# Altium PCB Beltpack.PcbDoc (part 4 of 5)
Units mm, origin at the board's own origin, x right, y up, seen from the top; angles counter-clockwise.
Board outline 85 x 81 mm, 4 copper layers (Top Layer, Inner-1, Inner_GND, Bottom Layer), stack 1.556 mm thick; 389 components, 291 nets, 1372 pads, 660 vias.
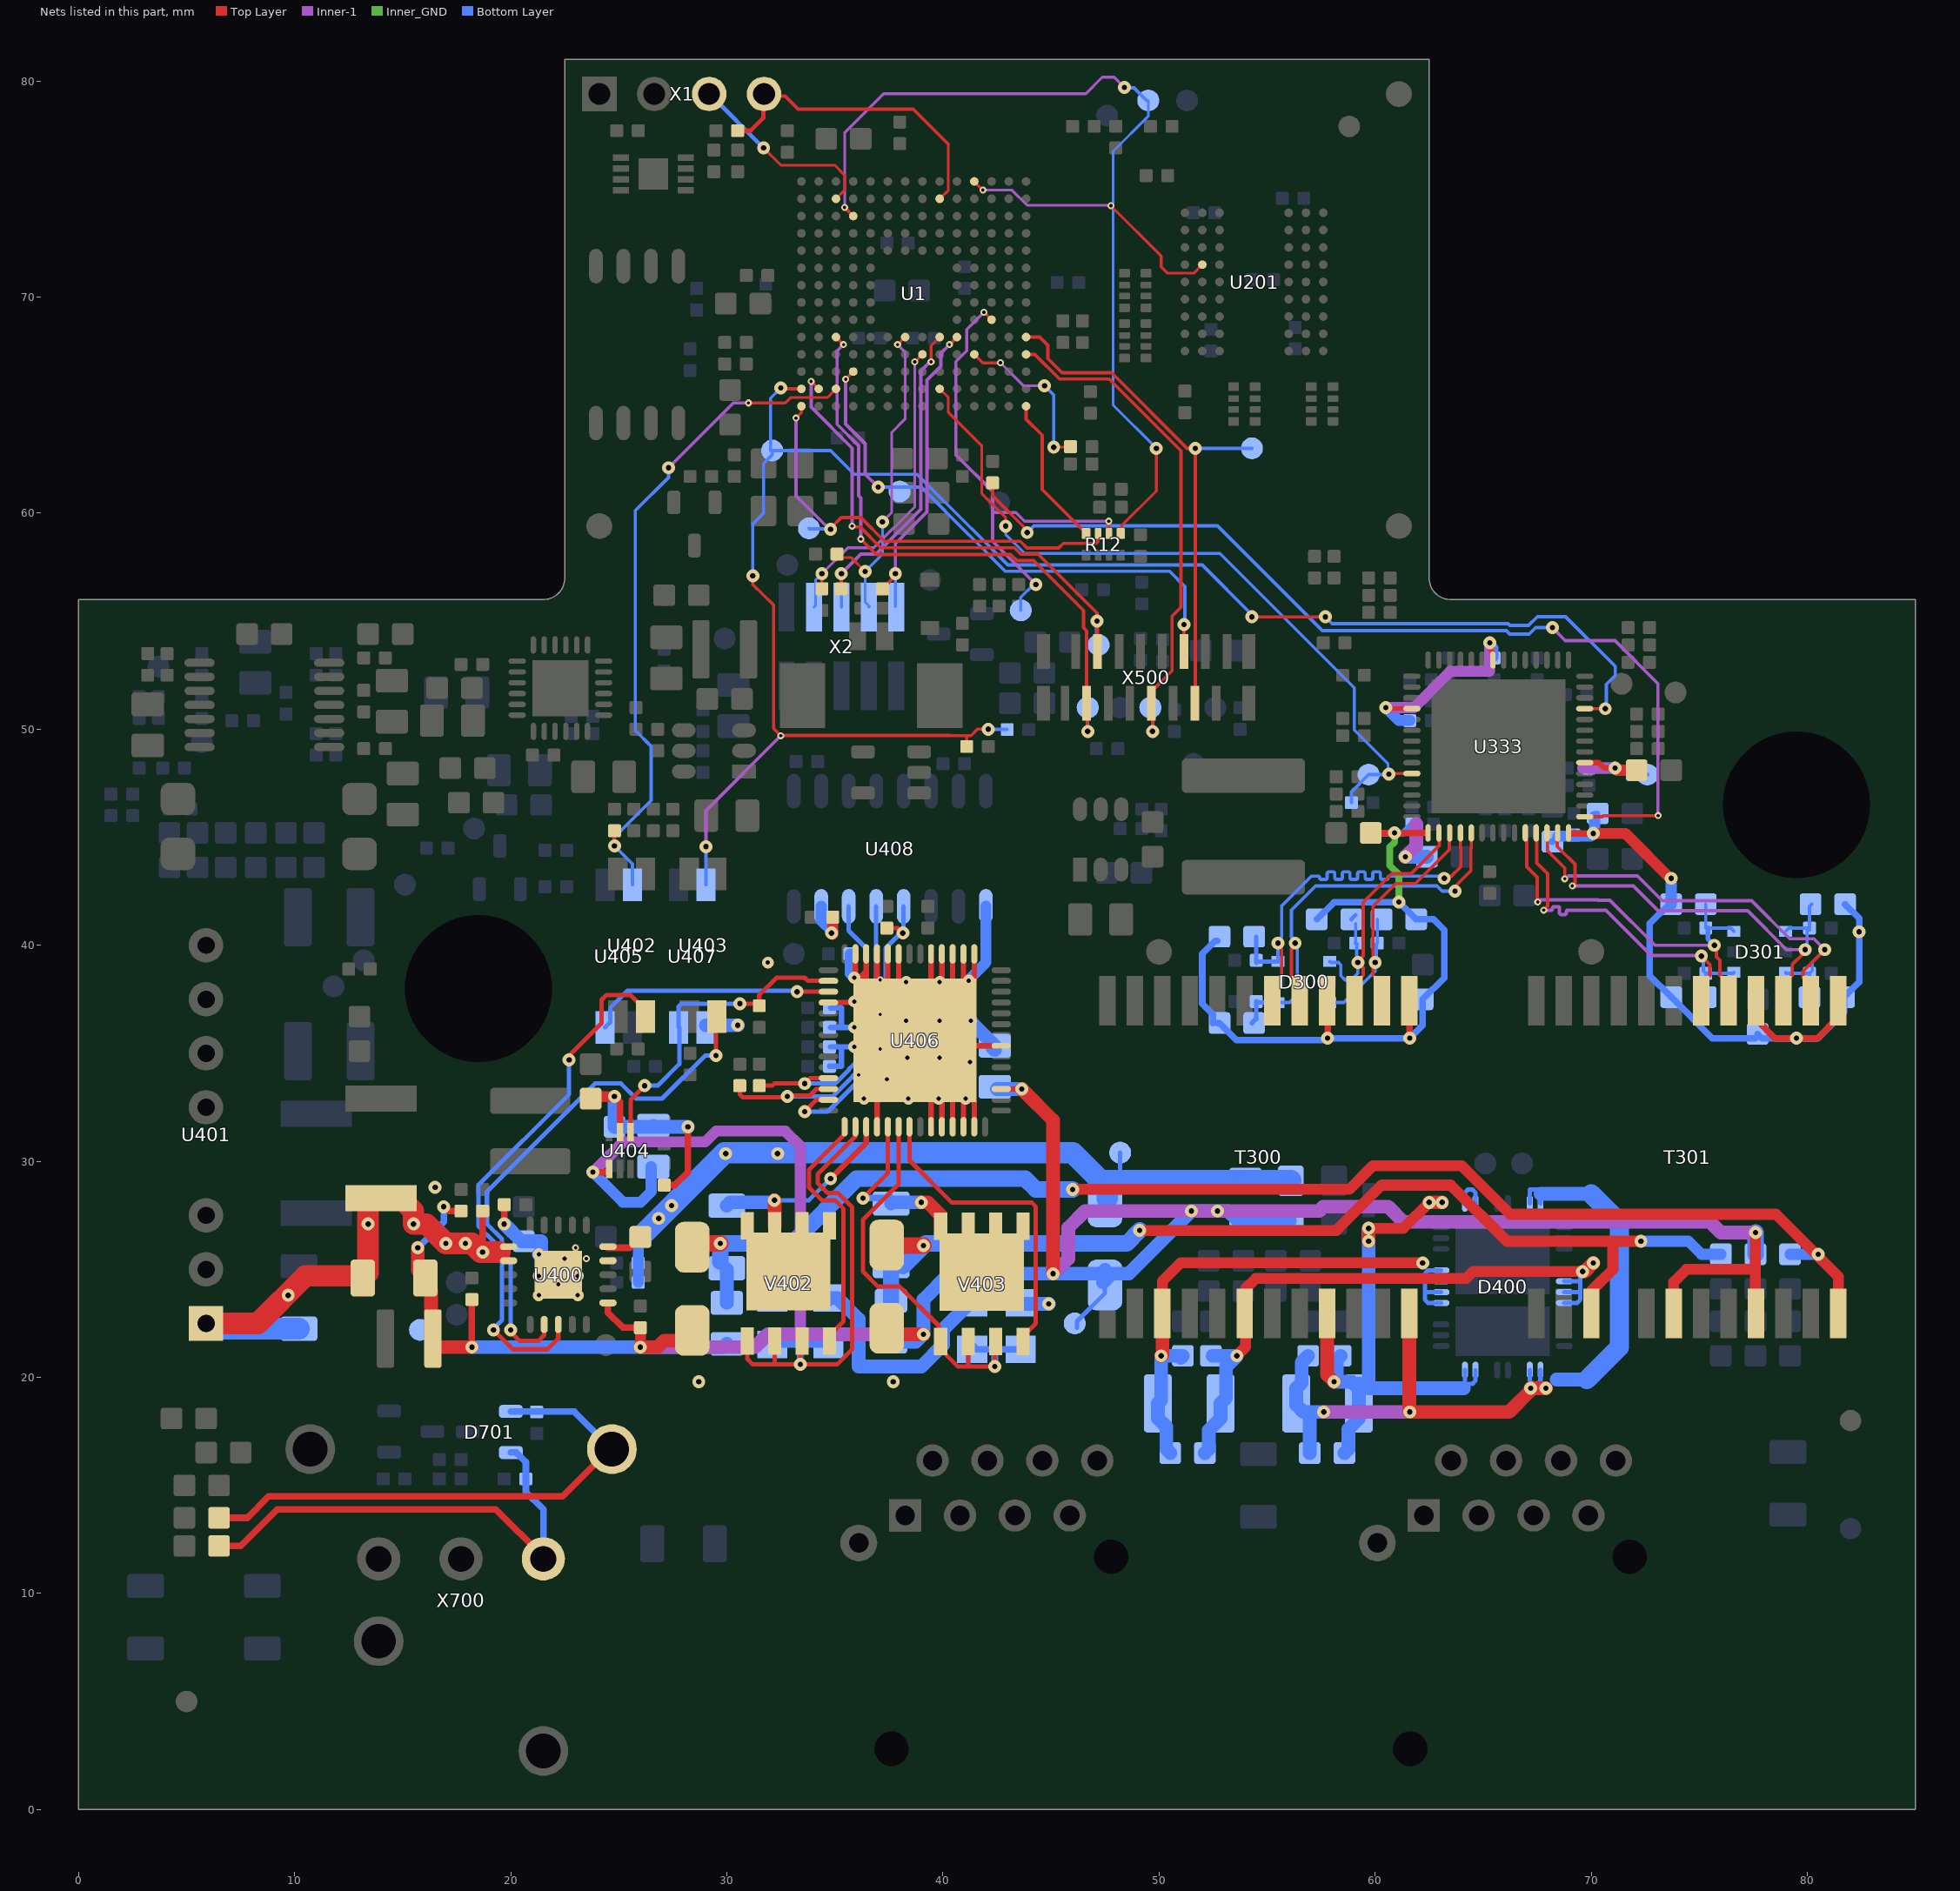
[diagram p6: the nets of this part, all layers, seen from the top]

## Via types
v1: diameter 0.6, hole 0.25, Top Layer to Bottom Layer, 460 vias
v2: diameter 0.325, hole 0.15, Top Layer to Inner-1, 145 vias
v3: diameter 0.55, hole 0.2, Top Layer to Bottom Layer, 41 vias
v4: diameter 0.325, hole 0.15, Top Layer to Inner-1, tented both sides, 8 vias
v5: diameter 1.6, hole 1.016, Top Layer to Bottom Layer, 5 vias
v6: diameter 0.6, hole 0.25, Top Layer to Bottom Layer, tented both sides, 1 vias

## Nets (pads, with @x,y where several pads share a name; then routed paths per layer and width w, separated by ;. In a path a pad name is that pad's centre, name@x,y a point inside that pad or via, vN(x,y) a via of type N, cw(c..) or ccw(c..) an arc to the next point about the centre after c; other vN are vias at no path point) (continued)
PERIPH_NRESET: R17.1 R210.1 TP9.1 U1.A2 U333.11 U407.2 | length 83.9
  Top Layer w0.152: v1(31.2,57.1) 31.2,56.7 31.678,56.222 31.684,56.222 32.162,55.744 32.162,50.038 v4(32.5,49.7) 32.511,49.711 40.312,49.711 40.323,49.7 41.1,49.7 ; v1(32.5,65.8) 32.55,65.75 U1.A2@33.45,65.75 ; R210.1@41.1,49.2 41.1,49.7 ; v1(42.1,50) 41.6,50 41.3,49.7 41.1,49.7 ; v1(54.3,55.2) v1(57.7,55.2) ; U333.11@69.7,50.95 v1(70.65,50.95)
  Inner-1 w0.152: v1(29.035,44.565) 29.035,46.235 v4(32.5,49.7)
  Bottom Layer w0.152: U407.2@29.035,42.8 v1(29.035,44.565) ; v1(31.2,57.1) 31.2,59.5 31.7,60 31.7,62.3 32.1,62.7 TP9.1@32.1,62.9 34.8,62.9 35.9,61.8 38.8,61.8 41.3,59.3 41.307,59.3 43.007,57.6 52,57.6 54.3,55.3 v1(54.3,55.2) ; TP9.1@32.024,62.9 32.024,65.324 v1(32.5,65.8) ; v1(42.1,50) 42.108,49.992 42.966,49.992 R17.1@42.975,49.983 ; v1@57.8,55.1 58.011,54.889 66.147,54.889 66.236,54.8 67.1,54.8 67.511,55.211 68.812,55.211 71.111,52.912 71.111,52.488 70.7,52.077 v1@70.7,51.2
PSE_D1: F400.2 U406.3 V402.5 V402.6 V402.7 V402.8 V402.9 | length 9.6
  Top Layer w0.254: v1(34.8,29.2) 36.45,30.85 U406.3@36.45,31.6
  Top Layer w0.635: v1(32.2,28.2) 32.215,28.185 V402.7@32.215,27.017
  Bottom Layer w0.203: v1(32.2,28.2) 33.8,28.2 v1(34.8,29.2)
  Bottom Layer w0.635: F400.2@30,27.948 30.152,28.1 32.1,28.1 v1(32.2,28.2)
PSE_D2: F401.2 U406.5 V403.5 V403.6 V403.7 V403.8 V403.9 | length 8.2
  Top Layer w0.203: v1(36.3,28.3) 37.45,29.45 U406.5@37.45,31.6 U406.5@37.442,31.592
  Top Layer w0.635: v1(39,28.1) 39.3,28.1 39.895,27.505 V403.8@39.895,26.99
  Bottom Layer w0.203: F401.2@37.5,28.3 F401.2@37.6,28.4
  Bottom Layer w0.305: v1(36.3,28.3) F401.2@37.5,28.3
  Bottom Layer w0.635: F401.2@37.6,28.048 37.652,28.1 v1(39,28.1)
PSE_G1: U406.1 V402.4 | length 11.9
  Top Layer w0.203: V402.4@34.755,21.683 34.755,21.955 35.4,22.6 35.4,27.8 35,28.2 34.4,28.2 33.8,28.8 33.8,29.6 35.45,31.25 U406.1@35.45,31.6
PSE_G2: U406.7 V403.4 | length 14.8
  Top Layer w0.203: U406.7@38.45,31.6 38.45,30.05 40.4,28.1 44.1,28.1 44.3,27.9 44.3,22.5 43.705,21.905 V403.4@43.705,21.656
PSE_N1: C326.1 C414.2 D402.A F400.1 T301.24 | length 63.1
  Top Layer w0.508: v1(46,28.7) 58.8,28.7 59.9,29.8 64,29.8 66.25,27.55 78.55,27.55 81.435,24.665 T301.24@81.435,22.96
  Top Layer w0.635: D402.A@28.275,25.775 D402.A@28.275,25.9 ; D402.A@28.4,25.9 D402.A@28.7,26.2
  Top Layer w0.762: D402.A@28.7,26.2 v1(29.7,26.2)
  Bottom Layer w0.508: F400.1@29.7,25.352 F400.1@30,25.052 ; C326.1@79.2,25.7 v1(80.5,25.7)
  Bottom Layer w0.635: C414.2@30,23.45 F400.1@30,25
  Bottom Layer w0.762: F400.1@29.7,25.352 v1(29.7,26.2) 33,26.2 36,29.2 43.8,29.2 44.3,28.7 v1(46,28.7)
PSE_N2: C327.1 C415.2 D403.A F401.1 T301.15 | length 48.1
  Top Layer w0.508: v1(49.1,26.8) 58.2,26.8 60.3,28.9 63.5,28.9 66.1,26.3 71,26.3 ; T301.15@70.005,22.96 70.005,24.005 71,25 71,26.3 ; v1(72.3,26.3) 71,26.3
  Top Layer w0.635: D403.A@37.6,26.125 D403.A@37.625,26.1
  Top Layer w0.762: D403.A@37.625,26.1 v1(39.1,26.1)
  Bottom Layer w0.508: v1(72.3,26.3) 74.5,26.3 75.1,25.7 C327.1@76,25.7
  Bottom Layer w0.635: F401.1@37.6,25.152 F401.1@38.152,25.152
  Bottom Layer w0.762: C415.2@37.6,23.55 F401.1@37.6,25.152 ; F401.1@38.152,25.152 v1(39.1,26.1) 39.2,26.2 48.5,26.2 v1(49.1,26.8)
PSE_NINT: R418.2 U1.C2 U405.4 | length 31
  Top Layer w0.127: v2(31,65.1) 32.7,65.1 32.949,65.349 34.649,65.349 35,65.7 U1.C2@35.05,65.75
  Top Layer w0.152: v1(24.8,44.6) 24.8,45 ; U1.C2@35,65.7 U1.C2@35.05,65.75
  Inner-1 w0.152: v1(27.3,62.1) 30.3,65.1 v2(31,65.1)
  Bottom Layer w0.152: U405.4@25.635,42.8 25.635,43.765 v1(24.8,44.6) 24.8,45 26.5,46.7 26.5,49.206 25.765,49.942 25.765,60.113 27.3,61.649 v1(27.3,62.1)
PSE_NIRQ: U405.2 U406.45 | length 11.5
  Top Layer w0.203: v1(33.25,37.85) U406.45@34.7,37.85
  Bottom Layer w0.203: U405.2@24.365,36.2 24.6,36.435 24.6,37.1 25.4,37.9 v1@33.3,37.9
PSE_NRES: R400.2 U404.6 U406.44 U407.4 | length 15
  Top Layer w0.203: U404.6@25.55,31.35 25.55,32.85 v1(26.2,33.5) ; v1(30.6,37.3) R400.2@31.5,37.3 ; R400.2@31.5,37.2 31.5,37.7 32.3,38.5 33.6,38.5 33.75,38.35 U406.44@34.7,38.35
  Bottom Layer w0.203: v1(26.2,33.5) 26.8,33.5 27.8,34.5 U407.4@27.8,36.2 ; U407.4@27.765,36.2 27.765,37.165 27.9,37.3 v1(30.6,37.3)
PSE_SCL: R415.2 U406.53 U408.14 | length 13.8
  Top Layer w0.203: R415.2@31.5,33.5 32.1,33.5 32.2,33.6 33.3,33.6 v1@33.7,33.6 ; v1@33.7,33.7 33.85,33.85 U406.53@34.7,33.85
  Bottom Layer w0.203: v1(33.6,33.6) 35.014,33.6 35.664,34.249 35.664,34.286 36.445,35.067 36.445,39.867 35.64,40.672 U408.14@35.64,41.8
PSE_SDAI: R413.2 U406.54 U408.13 | length 16.4
  Top Layer w0.203: R413.2@30.6,33.5 30.6,33.1 30.737,32.963 32.863,32.963 32.944,33.044 33.844,33.044 34.15,33.35 U406.54@34.7,33.35
  Bottom Layer w0.203: v1(32.8,33) 34.892,33 36.745,34.853 36.745,34.867 36.91,35.032 U408.13@36.91,41.8
PSE_SDAO: R404.2 U406.55 U408.12 | length 14.1
  Top Layer w0.203: v1@33.7,32.4 34.15,32.85 U406.55@34.7,32.85 ; R404.2@37.4,40.7 37.5,40.8 37.9,40.8 v1@38.2,40.5
  Bottom Layer w0.203: v1(33.6,32.3) 34.671,32.3 37.345,34.974 37.345,39.867 v1@38.095,40.617 ; v1@38.18,40.702 U408.12@38.18,41.8
  other v1: 38.145,40.567
PSE_SENSE1: R423.1 R424.1 U406.2 V402.1 V402.2 V402.3 | length 23.7
  Top Layer w0.203: V402.1@30.945,21.683 30.945,20.855 31.2,20.6 32.215,20.6 ; V402.2@32.215,21.683 32.215,20.6 ; V402.3@33.4,21.598 v1(33.4,20.6) ; U406.2@35.95,31.6 35.95,31.15 34.2,29.4 34.2,29 34.662,28.538 35.14,28.538 35.8,27.878 35.8,21.3 35.1,20.6 v1(33.4,20.6) ; 32.215,20.6 v1(33.4,20.6)
  Bottom Layer w0.305: R423.1@32.1,21.521 33.4,21.521 ; v1@33.3,20.6 33.4,20.7 33.4,21.521 ; R424.1@34.7,21.5 34.679,21.521 33.4,21.521
PSE_SENSE2: R425.1 R426.1 U406.6 V403.1 V403.2 V403.3 | length 21.3
  Top Layer w0.203: U406.6@37.95,31.6 37.95,28.95 36.3,27.3 36.3,24.9 37,24.2 38,24.2 39.8,22.4 39.8,21.751 V403.1@39.895,21.656 39.895,21.305 40.7,20.5 41.165,20.5 ; V403.2@41.165,21.656 41.165,20.5 ; V403.3@42.4,21.621 v1(42.4,20.5) 41.165,20.5
  Top Layer w0.305: V403.3@42.4,21.621 V403.3@42.435,21.656
  Bottom Layer w0.305: R426.1@41.35,21.294 42.416,21.294 ; R426.1@41.4,21.413 R426.1@41.433,21.446 ; v1(42.4,20.5) 42.4,21.278 42.416,21.294 ; 42.5,21.269 42.475,21.294 ; R425.1@43.6,21.294 42.475,21.294 ; 42.416,21.294 42.475,21.294
PW12: C321.1 C402.1 D400.19 D400.20 D400.33 D400.34 D404.1 T300.24 | length 38.2
  Top Layer w0.635: v1@61.585,18.4 T300.24@61.585,22.96 ; v1(61.6,18.4) 66.2,18.4 67.2,19.4 v1(67.2,19.5) v1(67.9,19.5)
  Inner-1 w0.635: v1(57.625,18.4) v1(61.6,18.4)
  Bottom Layer w0.203: D400.34@67.15,20.345 67.15,19.85 67.3,19.7 67.5,19.7 67.65,19.85 D400.33@67.65,20.345 ; D400.19@67.15,28.055 67.15,28.7 67.65,28.7 67.65,28.5 D400.20@67.65,28.055
  Bottom Layer w0.635: C321.1@56.9,21 56.6,20.7 56.6,19.75 56.35,19.5 D404.1@56.35,18.8 56.35,18.732 56.683,18.4 D404.1@56.75,18.4 ; C402.1@56.978,16.5 56.978,18.172 D404.1@56.75,18.4 ; v1(57.625,18.4) D404.1@56.75,18.4 ; 67.65,28.5 70,28.5 ; 68.4,19.9 69.8,19.9
  Bottom Layer w0.889: 69.8,19.9 71.3,21.4 71.3,27.2 70,28.5
PW36: C322.1 C402.2 D400.13 D400.14 D400.39 D400.40 D404.2 T300.21 | length 29.2
  Top Layer w0.508: v1(59.7,26.9) 61.3,26.9 v1(62.5,28.1)
  Top Layer w0.635: T300.21@57.775,22.96 57.775,20.125 v1(58.1,19.8) ; v1(59.7,26.3) v1(59.7,26.9) ; v1(62.5,28.1) v1(63.1,28.1)
  Bottom Layer w0.203: 64.1,19.5 64.3,19.7 64.5,19.7 64.65,19.85 D400.39@64.65,20.345 ; 64.15,19.85 D400.40@64.15,20.345 ; D400.13@64.15,28.055 64.15,28.55 64.3,28.7 64.5,28.7 64.65,28.55 D400.14@64.65,28.055
  Bottom Layer w0.635: C322.1@58.4,21 58.217,20.817 58.217,19.917 v1(58.1,19.8) 58.918,19.8 59.25,19.467 D404.2@59.25,18.8 59.25,18.1 58.76,17.61 58.76,16.682 C402.2@58.578,16.5 ; D404.2@59.25,19.7 D404.2@59.7,19.7 ; v1(59.7,26.9) v1(59.7,26.3) D404.2@59.7,19.7 ; 64.1,19.5 59.7,19.5 D404.2@59.7,19.7
PW45: C324.1 C405.1 D400.25 D400.26 D400.27 D400.28 D405.1 T300.18 | length 30.5
  Top Layer w0.508: v1(53.6,21) 54,21.4 54,22.925 T300.18@53.965,22.96 ; T300.18@54,23 54,24.1 54.476,24.576 64.2,24.576 64.524,24.9 v1(69.6,24.9) v1@69.7,24.9
  Top Layer w0.635: v1@69.7,24.9 v1(70.1,25.3)
  Bottom Layer w0.203: D400.28@68.75,23.45 69.35,23.45 69.5,23.6 69.5,23.9 ; D400.27@68.75,23.95 69.45,23.95 69.5,23.9 ; D400.26@68.75,24.45 69.5,24.45 ; D400.25@68.75,24.95 v1@69.5,24.95 ; v1@69.5,24.9 69.5,24.45 ; 69.5,23.9 69.5,24.45
  Bottom Layer w0.635: C405.1@52.119,16.5 52.302,16.682 52.302,17.552 52.85,18.1 D405.1@52.85,18.8 53.1,19.05 53.1,20.5 v1(53.6,21) C324.1@52.47,21
PW78: C325.1 C405.2 D400.5 D400.6 D400.7 D400.8 D405.2 T300.15 | length 26.2
  Top Layer w0.508: T300.15@50.155,22.96 50.155,24.455 51.013,25.313 v1@62.2,25.313
  Top Layer w0.635: v1(50.1,21) 50.155,21.055 T300.15@50.155,22.96
  Bottom Layer w0.203: D400.5@63.05,23.45 62.45,23.45 62.3,23.6 62.3,23.9 ; D400.6@63.05,23.95 62.35,23.95 62.3,23.9 ; D400.7@63.05,24.45 62.3,24.45 ; D400.8@63.05,24.95 62.45,24.95 62.3,24.8 62.3,24.45 ; 62.3,23.9 62.3,24.45
  Bottom Layer w0.635: C405.2@50.519,16.5 50.337,16.682 50.337,17.713 49.95,18.1 D405.2@49.95,18.8 50.1,18.95 v1(50.1,21) C325.1@51.1,21 C325.1@51,20.9
  other v1: 62.2,25.3
RAS: U1.L14 U201.F8 | length 12.8
  Top Layer w0.127: U1.L14@41.45,75.35 v2(41.85,74.95) ; v2(47.775,74.225) 50.1,71.9 50.1,71.4 50.398,71.102 51.601,71.102 U201.F8@52,71.5
  Inner-1 w0.127: v2(41.85,74.95) 43.2,74.95 43.902,74.248 47.752,74.248 v2(47.775,74.225)
ROT1A: TP1.1 U1.C5 X500.3 | length 28.5
  Top Layer w0.152: U1.C5@35.05,68.15 v2(35.4,67.8) ; v2(36.2,58.8) 36.913,58.087 43.136,58.087 43.423,57.8 44.2,57.8 46.5,55.5 46.5,54.7 46.65,54.55 X500.3@46.65,51.2 46.675,51.175 46.675,49.925 v1(46.7,49.9)
  Inner-1 w0.152: v2(35.4,67.8) 35.1,67.5 35.1,64.113 36.1,63.113 36.1,60.8 36.2,60.7 v2(36.2,58.8)
  Bottom Layer w0.152: v1(46.7,49.9) TP1.1@46.7,51
ROT1B: TP2.1 U1.B2 X500.4 | length 23.7
  Top Layer w0.127: v2(33.9,66.1) U1.B2@34.25,65.75
  Top Layer w0.152: v2(35.8,59.4) 35.833,59.367 36.162,59.367 37.128,58.4 43.3,58.4 43.6,58.1 44.4,58.1 47.125,55.375 v1(47.125,55) ; X500.4@47.15,53.6 v1@47.15,54.8
  Inner-1 w0.152: v2(33.9,66.1) 33.9,64.906 35.8,63.006 v2(35.8,59.4)
  Bottom Layer w0.152: v1(47.125,55) 47.104,54.979 47.104,53.996 TP2.1@47.2,53.9
ROT2A: TP10.1 U1.D3 X500.12 | length 25.2
  Top Layer w0.127: v2(35.5,66.2) U1.D3@35.85,66.55
  Top Layer w0.152: X500.12@51.15,53.6 v1(51.15,54.85)
  Inner-1 w0.152: v2(35.5,66.2) 35.5,64.119 36.4,63.219 36.4,61.8 v1(37,61.2)
  Bottom Layer w0.152: v1(37,61.2) 38.994,61.2 41.194,59 41.2,59 42.887,57.313 50.487,57.313 51.2,56.6 v1@51.2,54.9
ROT2B: TP11.1 U1.P5 X500.13 | length 24.8
  Top Layer w0.152: U1.P5@43.853,68.153 U1.P5@43.85,68.15 44.475,68.15 44.853,67.772 44.853,67.153 45.508,66.499 47.801,66.499 51.3,63 v1(51.675,63) 51.675,51.225 X500.13@51.65,51.2
  Bottom Layer w0.152: v1(51.675,63) TP11.1@54.3,63
RTN: C401.2 C406.1 C407.2 C409.2 C410.2 C411.2 C412.1 C413.2 C416.1 R416.1 R417.2 R423.2 R424.2 R425.2 R426.2 R427.1 R428.1 R429.1 R430.1 TP410.1 U400.11 U400.12 U401.1 U404.7 U406.4 U406.9 U406.10 U406.11 U406.12 U406.13 U406.21 U406.30 U406.31 U406.32 U406.33 U406.34 U406.37 U406.38 U406.39 U406.40 U406.41 U406.46 U406.57 U407.3 U408.9 U408.15 | length 119.4
  Top Layer w0.254: U406.46@34.7,37.35 U406.57@36.95,37.35 ; v3(35.9,38.5) v3@35.95,38.5 ; U406.41@35.95,39.6 v3@35.95,38.5 ; U406.40@36.45,39.6 36.45,38.8 ; U406.4@36.95,31.6 36.95,33.85 U406.57@38.238,35.138 ; U406.39@36.95,39.6 U406.57@36.95,37.35 ; U406.38@37.45,39.6 U406.57@37.45,36.85 ; U406.37@37.95,39.6 37.95,36.35 U406.57@37.45,36.85 ; U406.57@38.125,35.3 U406.57@38.4,35.3 ; U406.57@39.025,35.35 U406.21@42.7,35.35 ; U406.9@39.45,31.6 U406.57@39.45,34.85 ; U406.57@39.45,36.35 U406.34@39.45,39.6 ; v3(39.8,32.9) 39.95,32.75 U406.10@39.95,31.6 ; U406.57@39.95,34.35 U406.57@40.45,33.85 ; U406.57@39.95,36.85 U406.33@39.95,39.6 ; U406.11@40.45,31.6 U406.57@40.45,33.85 ; U406.57@40.45,37.35 U406.32@40.45,39.6 ; U406.12@40.95,31.6 U406.57@40.95,33.25 ; U406.31@40.95,39.6 40.95,37.85 41.45,38.35 U406.30@41.45,39.6 ; U406.13@41.45,31.6 41.45,32.75 U406.57@40.95,33.25 ; v3@35.95,38.5 35.95,38.35 U406.57@36.45,37.85 ; v3@35.95,38.5 36.15,38.5 36.45,38.8 ; U406.57@36.45,37.85 36.45,38.8 ; U406.57@36.45,37.85 U406.57@36.95,37.35 ; U406.57@36.95,37.35 U406.57@37.45,36.85 ; U406.57@40.45,33.85 40.95,33.35 U406.57@40.95,33.25
  Top Layer w0.305: v1(18.7,25.8) R416.1@18.7,27.7 ; v1(24.8,33) 25.05,32.75 U404.7@25.05,31.35 ; R417.2@27.1,28.9 27.6,28.9 28.2,29.5 v1(28.2,31.6)
  Top Layer w0.508: C411.2@23.7,33 v1(24.8,33) ; v1@34.9,40.5 C416.1@34.9,41.3
  Top Layer w1: U401.1@5.9,22.5 8.3,22.5 10.5,24.7 13.093,24.7 13.093,24.249 13.152,24.308 C401.2@13.152,24.6 13.4,24.848 v1(13.4,27.1) 13.4,28.2 13.5,28.3 C406.1@14,28.3 14.9,28.3 15.5,27.7 v1(15.5,27.1) 16.1,27.1 v1(17,26.2) v1(17.9,26.2) 18.2,26.2 18.6,25.8 v1(18.7,25.8) 19.5,25.8
  Bottom Layer w0.254: R430.1@34.75,34.4 R430.1@34.8,34.4 ; R429.1@34.8,35.3 35.2,35.3 ; R428.1@34.8,36.2 v3@35.8,36.2 ; R427.1@34.8,37.1 35.3,37.1 35.3,36.2 ; 35.2,34.4 R430.1@34.8,34.4 ; v3(35.9,35.3) 35.2,35.3 ; R430.1@34.8,34.4 35.3,34.4 35.3,35.3 35.2,35.3
  Bottom Layer w0.508: U408.15@34.37,41.8 34.37,41.142 34.845,40.667 v1(34.845,40.567) ; C412.1@35.7,39.6 35.7,38.7 v3(35.9,38.5) ; v3@41.145,38.367 41.99,39.212 U408.9@41.99,41.8
  Bottom Layer w0.635: v1@24.8,32.9 C410.2@24.8,31.6 C409.2@26.65,31.6 ; C409.2@26.6,31.65 C409.2@26.65,31.6 ; v1(28.2,31.6) C409.2@26.65,31.6 ; U407.3@29.035,36.3 v1(30.5,36.3) ; R423.2@32.1,23.68 34.62,23.68 R424.2@34.7,23.6 ; R424.2@34.7,23.68 35.12,23.68 36.1,22.7 36.1,20.5 39,20.5 40,21.5 40,22.2 41.253,23.453 R426.2@41.35,23.453 R425.2@43.6,23.453 43.653,23.4 v1(44.9,23.4) ; v3(41.3,36.5) 41.3,36.45 C413.2@42.4,35.35 ; C413.2@42.3,35.25 C413.2@42.4,35.15
  Bottom Layer w1: U401.1@5.8,22.4 5.948,22.252 C407.2@10.2,22.252
  other v1: 28.7,19.8 37.7,19.8 9.7,23.8 16.5,28.8
  other v3: 36.35,32.9 38.4,32.9 41.05,32.9 37.4,33.8 41.25,34.6 38.35,34.8 39.85,34.8 35.9,36.2 38.3,36.5 39.85,36.5 35.9,37.4 38.3,38.3 39.85,38.3 41.195,38.367 31.9,39.2
  other v4: 36.1,34 37.1,35.2 37.1,36.8 37.1,38.4
RXA_N: C328.1 D300.6 R307.2 T300.6 U333.46 | length 20.8
  Top Layer w0.152: T300.6@55.235,37.44 55.235,38.21 55.539,38.514 55.552,38.514 55.671,38.633 55.671,39.807 55.5,39.979 v1(55.5,40.1) ; v1(63.2,43.1) 63.286,43.186 63.512,43.186 63.971,43.645 63.971,44.48 63.951,44.5 63.951,45.199 U333.46@63.95,45.2
  Bottom Layer w0.152: D300.6@55.5,39.25 v1(55.5,40.1) 55.5,40.221 55.671,40.392 55.671,41.818 57.053,43.2 57.075,43.2 57.363,43.2 cw(c57.363,43.136) 57.427,43.136 ccw(c57.515,43.136) 57.515,43.048 57.692,43.048 ccw(c57.692,43.136) 57.78,43.136 57.78,43.2 57.78,43.312 cw(c57.868,43.312) 57.868,43.4 58.044,43.4 cw(c58.044,43.312) 58.132,43.312 58.132,43.2 58.132,43.136 ccw(c58.22,43.136) 58.22,43.048 58.396,43.048 ccw(c58.396,43.136) 58.484,43.136 58.484,43.2 58.484,43.312 cw(c58.573,43.312) 58.573,43.4 58.749,43.4 cw(c58.749,43.312) 58.837,43.312 58.837,43.2 58.837,43.136 ccw(c58.925,43.136) 58.925,43.048 59.101,43.048 ccw(c59.101,43.136) 59.189,43.136 59.189,43.2 59.189,43.312 cw(c59.277,43.312) 59.277,43.4 59.454,43.4 cw(c59.454,43.312) 59.542,43.312 59.542,43.2 59.542,43.136 ccw(c59.63,43.136) 59.63,43.048 59.806,43.048 ccw(c59.806,43.136) 59.894,43.136 59.894,43.2 59.894,43.312 cw(c59.982,43.312) 59.982,43.4 60.158,43.4 cw(c60.158,43.312) 60.246,43.312 60.246,43.2 60.246,43.136 ccw(c60.334,43.136) 60.334,43.048 60.511,43.048 ccw(c60.511,43.136) 60.599,43.136 cw(c60.663,43.136) 60.663,43.2 60.775,43.2 v1@63.2,43.2
  Bottom Layer w0.193: C328.1@54.5,39.2 C328.1@54.5,39.3 R307.2@54.5,40.4 ; C328.1@54.55,39.25 D300.6@55.5,39.25
  Bottom Layer w0.22: C328.1@54.5,39.2 C328.1@54.55,39.25
RXA_P: C323.1 D300.4 R308.2 T300.5 U333.47 | length 21.1
  Top Layer w0.152: v1(56.3,40.1) 56.3,39.979 56.129,39.807 56.129,38.573 56.188,38.514 56.201,38.514 56.505,38.21 T300.5@56.505,37.44 ; v1(63.7,42.5) 63.786,42.586 63.786,42.812 64.429,43.455 64.429,44.48 64.449,44.5 U333.47@64.449,45.199
  Top Layer w0.193: U333.47@64.449,45.199 U333.47@64.45,45.2
  Bottom Layer w0.152: D300.4@55.5,37.35 56.05,37.35 56.4,37.7 v1@56.4,40 ; v1(56.3,40.1) 56.3,40.221 56.129,40.393 56.129,41.629 57.243,42.743 62.857,42.743 63.1,42.5 v1(63.7,42.5)
  Bottom Layer w0.193: R308.2@54.5,36.6 C323.1@54.5,37.4 ; C323.1@54.55,37.35 D300.4@55.5,37.35
  Bottom Layer w0.22: R308.2@54.3,36.4 R308.2@54.5,36.6 ; C323.1@54.5,37.4 C323.1@54.55,37.35
RXB_N: C333.1 D301.1 R315.2 T301.6 U333.53 | length 18.3
  Top Layer w0.16: U333.53@67.45,45.2 67.467,45.183 67.467,45.09 67.48,45.078 67.48,43.82 67.981,43.319 67.981,41.824 67.8,41.643 v2(67.8,41.625) ; T301.6@75.085,37.44 75.085,38.21 75.385,38.51 75.394,38.51 75.488,38.604 75.488,39.112 75.142,39.458 v1@75.1,39.458
  Top Layer w0.22: v1@75.1,39.458 v1(75.1,39.5)
  Inner-1 w0.16: v2(67.8,41.625) 67.8,41.635 67.807,41.635 67.818,41.625 68.05,41.625 68.13,41.625 ccw(c68.13,41.705) 68.21,41.705 68.21,41.708 cw(c68.29,41.708) 68.29,41.788 68.45,41.788 cw(c68.45,41.708) 68.53,41.708 68.53,41.625 68.53,41.505 ccw(c68.61,41.505) 68.61,41.425 68.77,41.425 ccw(c68.77,41.505) 68.85,41.505 68.85,41.545 cw(c68.93,41.545) 68.93,41.625 69.875,41.625 70.675,41.625 72.775,39.525 75.162,39.525 v1@75.168,39.532
  Bottom Layer w0.16: v1@75.168,39.532 v1@75.2,39.5 ; v1@75.184,39.416 75.184,38.816 C333.1@75.3,38.7 ; R315.2@75.3,37.6 C333.1@75.3,38.7 ; D301.1@76.6,38.75 76.55,38.7 C333.1@75.3,38.7
RXB_P: C334.1 D301.3 R319.2 T301.5 U333.52 | length 18.5
  Top Layer w0.16: U333.52@66.95,45.2 66.967,45.183 66.967,44.933 67.015,44.885 67.015,43.628 67.5,43.143 v2@67.5,42 ; v1@75.7,39.805 75.776,39.805 75.784,39.797 75.784,39.473 75.952,39.305 75.952,38.604 76.046,38.51 76.055,38.51 76.355,38.21 T301.5@76.355,37.44
  Top Layer w0.22: v1(75.7,40) 75.7,39.997 v1@75.701,39.999
  Inner-1 w0.16: v2@67.5,42 67.6,42.1 70.3,42.1 70.31,42.09 70.868,42.09 72.957,40 v1(75.7,40)
  Bottom Layer w0.16: C334.1@75.3,40.8 R319.2@75.3,41.9 ; C334.1@75.4,40.8 76.45,40.8 D301.3@76.6,40.65
  Bottom Layer w0.22: C334.1@75.4,40.8 75.4,40.3 75.696,40.004 75.7,40.004 75.696,40 v1(75.7,40)
  other v2: 67.525,42
SPI_MISO: TP7.1 U1.P4 X500.9 | length 23.7
  Top Layer w0.152: U1.P4@43.85,67.35 44.25,67.35 45.389,66.211 47.682,66.211 51.011,62.882 51.011,55.636 50.6,55.225 50.6,52.7 49.65,51.75 X500.9@49.65,51.2 ; X500.9@49.625,51.175 49.7,51.1 v1(49.7,49.9)
  Bottom Layer w0.152: TP7.1@49.6,51 49.7,50.9 v1(49.7,49.9)
SPI_MOSI: R12.2 TP5.1 U1.M6 | length 22.8
  Top Layer w0.127: v2(41.9,69.3) U1.M6@42.25,68.95
  Top Layer w0.152: R12.2@47.675,59.059 v2(47.675,59.625)
  Inner-1 w0.127: 40.6,63.8 40.6,67.011 41.1,67.511 41.1,68.5 v2(41.9,69.3)
  Inner-1 w0.152: 40.6,63.8 40.6,62.7 42.3,61 42.3,60.025 ; v1(44.3,56.7) 42.3,58.7 42.3,60.025 ; v2(47.675,59.625) 43.775,59.625 43.375,60.025 42.3,60.025
  Bottom Layer w0.152: TP5.1@43.6,55.5 43.6,56.1 44.2,56.7 v1(44.3,56.7)
SPI_NCS0: R12.4 U1.P1 | length 7
  Top Layer w0.152: U1.P1@43.85,64.95 43.85,64.35 44.589,63.611 44.589,61.096 R12.4@46.625,59.059
SPI_SCK: R12.1 TP6.1 U1.D12 | length 41.7
  Top Layer w0.127: R12.1@48.225,59.059 48.25,59.084 48.25,59.4 49.875,61.025 v1(49.875,63)
  Top Layer w0.152: v2(35.45,74.15) U1.D12@35.85,73.75
  Inner-1 w0.127: v2(35.45,74.15) 35.45,77.6 37.262,79.412 46.612,79.412 47.373,80.173 47.927,80.173 v1(48.4,79.7)
  Bottom Layer w0.127: TP6.1@49.5,79.1 49.5,78.371 47.875,76.745 47.875,65 v1(49.875,63)
  Bottom Layer w0.152: v1(48.4,79.7) 48.411,79.689 48.84,79.689 TP6.1@49.429,79.1
SPK+: C718.1 D701.1 L705.1 X700.4 | length 24.9
  Top Layer w0.305: L705.1@6.5,13.5 7.8,13.5 8.8,14.5 22.4,14.5 X700.4@24.68,16.78
  Bottom Layer w0.305: D701.1@20.004,18.426 22.934,18.426 24.56,16.8 X700.4@24.7,16.8
SPK-: C719.1 D701.2 L704.1 X700.3 | length 22.3
  Top Layer w0.305: L704.1@6.4,12.2 L704.1@6.5,12.2 7.5,12.2 9.2,13.9 19.31,13.9 X700.3@21.51,11.7
  Bottom Layer w0.305: D701.2@20.004,16.526 20.254,16.526 20.7,16.08 C719.1@20.7,15.3 20.7,14.7 21.51,13.89 X700.3@21.51,11.7
SW_CLK: R20.2 U333.1 | length 45
  Top Layer w0.152: R20.2@42.3,61.3 42.3,60.8 43.9,59.2 v1(43.9,59.1) ; U333.1@69.7,45.95 70.5,45.95 70.55,46 v2(73.1,46)
  Inner-1 w0.152: v1(68.2,54.7) 68.8,54.1 71.1,54.1 73.089,52.111 73.089,46.011 v2(73.1,46)
  Bottom Layer w0.152: v1(43.9,59.1) 44.211,59.411 52.7,59.411 57.55,54.561 66.068,54.561 66.229,54.4 67.127,54.4 67.427,54.7 v1(68.2,54.7)
SWI_CS: R12.3 TP4.1 U1.A1 | length 21.2
  Top Layer w0.127: v4(33.2,64.4) 33.45,64.65 U1.A1@33.45,64.95
  Top Layer w0.152: v1@34.8,59.3 35.3,59.8 36.2,59.8 37.3,58.7 43.577,58.7 43.888,58.389 45.364,58.389 45.573,58.598 47.098,58.598 47.175,58.675 R12.3@47.175,59.059
  Inner-1 w0.152: v4(33.2,64.4) 33.2,60.8 v1@34.7,59.3
  Bottom Layer w0.152: TP4.1@33.8,59.3 33.825,59.275 34.825,59.275 v1@34.9,59.2
  other v1: 34.8,59.25
SWI_IRQ: R335.1 TP301.1 U1.J2 U333.38 | length 35.1
  Top Layer w0.127: U1.J2@39.85,65.75 40.25,65.35 40.25,64.65 41.8,63.1 41.8,60.9 42.9,59.8 v1(42.9,59.4)
  Top Layer w0.152: v1@60.862,47.95 U333.38@61.7,47.95
  Bottom Layer w0.127: v1(42.9,59.4) 42.9,59.024 43.788,58.137 52.822,58.137 59.038,51.921 59.038,49.962 60.6,48.4 v1@60.6,47.925
  Bottom Layer w0.152: R335.1@58.9,46.6 58.9,47.1 TP301.1@59.7,47.9 v1@60.612,47.9
  other v1: 60.637,47.925
TCK: R9.1 U1.G5 X2.4 | length 15.3
  Top Layer w0.127: R9.1@35.2,58.1 35.2,58.074 35.336,57.938 35.761,57.938 v1(36.4,57.3) ; v2(37.9,67.8) U1.G5@38.25,68.15
  Inner-1 w0.127: v1(37.2,59.6) 37.626,60.026 37.626,63.731 38.25,64.355 38.25,67.45 v2(37.9,67.8)
  Bottom Layer w0.127: X2.4@36.57,55.65 36.6,55.68 36.4,55.88 v1(36.4,57.3) 36.5,57.3 36.45,57.35 37.2,58.1 v1(37.2,59.6)
TDI: R5.1 U1.H4 X2.8 | length 15.3
  Top Layer w0.127: v2(38.7,67) U1.H4@39.05,67.35
  Top Layer w0.152: R5.1@34.4,56.4 v1(34.4,57.2)
  Inner-1 w0.127: v1(34.4,57.2) 35.6,58.4 36.8,58.4 38.7,60.3 v2(38.7,67)
  Bottom Layer w0.127: X2.8@34.03,55.65 34.1,55.72 34.1,56.9 v1(34.4,57.2)
TDO: R6.1 U1.J5 X2.6 | length 15.6
  Top Layer w0.127: v2@39.4,67 39.448,67.048 39.448,67.749 U1.J5@39.85,68.15
  Top Layer w0.152: R6.1@35.3,56.4 v1(35.3,57.2)
  Inner-1 w0.152: v1(35.3,57.2) 36.2,58.1 36.9,58.1 38.975,60.175 38.975,66.575 v2@39.4,67
  Bottom Layer w0.152: X2.6@35.3,55.65 v1(35.3,57.2)
  other v2: 39.45,67
TMS: R7.1 U1.K5 X2.2 | length 14.6
  Top Layer w0.152: R7.1@37.2,56.5 37.8,57.1 v1(37.8,57.2) ; v2(40.3,67.8) U1.K5@40.65,68.15
  Inner-1 w0.152: v1(37.8,57.2) 37.8,58.594 39.262,60.056 39.262,66.162 39.9,66.8 39.9,67.4 v2(40.3,67.8)
  Bottom Layer w0.152: X2.2@37.8,55.69 v1(37.8,57.2)
TPH: U400.18 U402.2 | length 25.2
  Top Layer w0.203: v1(19.2,22.2) 20.1,21.3 21.7,21.3 22.2,21.8 U400.18@22.2,22.45 ; v1(22.7,34.7) 22.7,34.9 24.2,36.4 24.2,37.47 24.417,37.687 25.548,37.687 26.235,37 U402.2@26.235,36.7
  Bottom Layer w0.203: v1(19.2,22.2) 19.2,22.255 19.6,22.655 19.6,25.322 19.237,25.685 19.237,26.263 18.5,27 18.5,28.9 22.7,33.1 v1(22.7,34.7)
TPL: U400.17 U403.2 | length 24.8
  Top Layer w0.203: v1(20,22.2) 20,22.1 20.4,21.7 21.3,21.7 21.55,21.95 U400.17@21.55,22.45 ; v1(29.5,34.9) U403.2@29.5,36.6 ; U403.2@29.5,36.665 U403.2@29.535,36.7
  Bottom Layer w0.203: v1(20,22.2) 20,22.7 20,25.4 19.6,25.8 19.6,26.4 18.9,27.1 18.9,28.6 19.4,29.1 23.9,33.6 25.1,33.6 25.8,32.9 27,32.9 29,34.9 v1(29.5,34.9)
TRST: R8.1 U1.L4 | length 7.8
  Top Layer w0.127: U1.L4@41.45,67.35 41.85,66.95 42.65,66.95 v2(42.66,66.96) ; v1(45.125,63.05) 45.8,63.05 45.85,63 45.9,63.05 R8.1@45.8,62.95
  Inner-1 w0.127: v2(42.66,66.96) 43.719,65.9 v1(44.7,65.9)
  Bottom Layer w0.152: v1(44.7,65.9) 45.125,65.475 v1(45.125,63.05)
TXA_N: C319.1 D300.1 R305.2 T300.3 U333.44 | length 14.7
  Top Layer w0.152: T300.3@59.045,37.6 59.045,38.21 59.443,38.608 59.443,38.957 v1(59.2,39.2) 59.2,39.257 59.443,39.5 59.443,41.989 60.768,43.315 61.668,43.315 62.971,44.618 62.971,44.835 62.969,44.837 62.969,45.181 U333.44@62.95,45.2
  Bottom Layer w0.152: D300.1@57.9,39.25 57.95,39.2 58.3,39.2 58.411,39.089 58.411,38.589 58.6,38.4 58.9,38.4 59.2,38.7 59.2,39.15 v1@59.125,39.225 ; C319.1@59.1,40.1 R305.2@59.1,41 ; v1@59.15,39.25 C319.1@59.15,40.05
  Bottom Layer w0.193: R305.2@58.9,41.2 R305.2@59.1,41.4 ; C319.1@59.1,40.1 C319.1@59.15,40.05 ; v1@59.125,39.225 v1@59.15,39.25
TXA_P: C320.1 D300.3 R306.2 T300.2 U333.45 | length 14.8
  Top Layer w0.152: 59.9,39.5 59.9,41.8 60.957,42.857 61.857,42.857 63.429,44.429 63.429,44.835 63.431,44.837 63.431,45.181 U333.45@63.45,45.2 ; v1(60,39.2) 59.9,39.1 59.9,38.612 59.998,38.514 60.011,38.514 60.315,38.21 T300.2@60.315,37.44
  Bottom Layer w0.152: D300.3@57.9,37.35 58.55,37.35 60,38.8 v1(60,39.2) 60.05,39.25 60.05,40.05 C320.1@60.1,40.1 R306.2@60.101,41.2
TXB_N: C335.1 D301.4 R313.2 T301.3 U333.55 | length 20.9
  Top Layer w0.152: U333.55@68.45,45.2 68.431,45.181 68.431,44.837 68.429,44.835 68.429,44.571 68.6,44.4 69.25,43.75 v2@69.25,42.851 ; T301.3@78.895,37.44 78.895,38.21 79.199,38.514 79.212,38.514 79.301,38.603 79.301,39.101 79.814,39.614 79.814,39.714 v1(79.9,39.8)
  Inner-1 w0.152: v2(69.125,42.75) 71.95,42.75 73.1,41.6 77.236,41.6 79.036,39.8 v1(79.9,39.8)
  Bottom Layer w0.152: D301.4@79,40.65 79.15,40.8 80,40.8 C335.1@80.05,40.75 ; v1(79.9,39.8) 79.986,39.886 79.986,40.686 C335.1@80.05,40.75 ; C335.1@80.1,40.7 C335.1@80.05,40.75 ; R313.2@80.2,41.9 80.1,41.8 C335.1@80.1,40.8 C335.1@80.05,40.75
TXB_P: C336.1 D301.6 R314.2 T301.2 U333.54 | length 22.2
  Top Layer w0.152: U333.54@67.95,45.2 67.969,45.181 67.969,44.837 67.971,44.835 67.971,44.382 68.411,43.943 68.775,43.578 68.775,43.1 v2@68.789,43.086 ; T301.2@80.2,37.5 80.2,38.1 79.8,38.5 79.8,38.789 80.8,39.789 v1(80.8,39.8)
  Inner-1 w0.152: v2(68.775,43.075) 68.803,43.075 68.936,43.207 72.139,43.207 73.289,42.057 77.425,42.057 79.182,40.3 80.3,40.3 v1(80.8,39.8)
  Bottom Layer w0.152: D301.6@79,38.75 79,38.7 C336.1@80.1,38.7 ; R314.2@80.1,37.6 C336.1@80.1,38.7 ; v1@80.6,39.6 80.229,39.229 80.229,38.829 C336.1@80.1,38.7
UART2_RXD: R13.2 U1.J13 X1.4 | length 14.6
  Top Layer w0.127: U1.J13@39.85,74.55 40.25,74.95 40.25,77.074
  Top Layer w0.152: X1.4@31.7,79.3 32.7,79.3 33.3,78.7 38.624,78.7 40.25,77.074
  Top Layer w0.203: R13.2@30.5,77.7 31.1,77.7 31.7,78.3 X1.4@31.7,79.3
UART2_TXD: U1.C13 X1.3 | length 9.1
  Top Layer w0.127: v1(31.7,76.9) 32.5,76.1 35,76.1 35.45,75.65 35.45,74.95 U1.C13@35.05,74.55
  Bottom Layer w0.203: X1.3@29.2,79.4 v1(31.7,76.9)
VBIASTXRX1: C317.1 C318.1 C330.2 L303.2 R305.1 R306.1 R307.1 R308.1 T300.1 T300.4 U333.43 | length 37.7
  Top Layer w0.305: T300.4@57.775,37.44 57.8,37.415 v1(57.8,35.7) ; L303.2@59.8,45.2 v1(60.9,45.2) U333.43@62.4,45.2 ; T300.1@61.585,37.44 61.592,37.432 61.592,35.708 v1(61.6,35.7)
  Inner_GND w0.305: v1(60.9,45.2) 60.9,44.775 60.675,44.55 60.675,43.7 61.1,43.275 v1(61.1,42)
  Bottom Layer w0.305: R308.1@52.5,36.4 52.5,36.8 52,37.3 52,39.6 52.6,40.2 R307.1@52.7,40.2 ; R308.1@52.7,36.4 R308.1@52.8,36.4 53.587,35.613 57.633,35.613 57.72,35.7 v1(57.8,35.7) v1(61.6,35.7) 62.2,36.3 C330.2@62.2,37.5 63.2,38.5 63.2,40.7 62.7,41.2 R306.1@61.9,41.2 v1(61.1,42) 58.1,42 R305.1@57.3,41.2 ; C317.1@59.8,45.2 v1(60.9,45.2) 61.3,45.2 C318.1@61.7,45.6
VBIASTXRX2: C312.1 C313.1 C332.2 L302.2 R313.1 R314.1 R315.1 R319.1 T301.1 T301.4 U333.56 | length 36.2
  Top Layer w0.305: U333.56@69,45.2 69.025,45.175 v1(70.1,45.175) ; T301.4@77.625,37.44 77.625,36.575 78.5,35.7 v1(79.5,35.7) 80.465,35.7 81.435,36.67 T301.1@81.435,37.44
  Top Layer w0.508: v1(70.1,45.175) 71.575,45.175 v1@73.675,43.075 ; v1(82.4,40.625) v1@82.425,40.625
  Bottom Layer w0.305: C312.1@68.2,44.8 C312.1@68.45,45.05 ; C313.1@69.2,45.2 C313.1@69.35,45.05 ; v1(70.1,45.175) v1@70.156,45.231 ; L302.2@70.156,45.956 L302.2@70.275,46.075 ; R319.1@73.7,41.9 73.6,41.9 72.7,41 72.7,38.6 R315.1@73.7,37.6 75.6,35.7 77.6,35.7 C332.2@77.7,35.8 ; C332.2@77.7,35.9 77.9,35.7 v1(79.5,35.7) 80.5,35.7 81.7,36.9 R314.1@81.7,37.6 82.048,37.948 82.4,38.3 v1(82.4,40.625) 82.4,41.25 R313.1@81.75,41.9
  Bottom Layer w0.508: C312.1@68.45,45.05 69.15,45.05 C313.1@69.2,45.1 ; C313.1@69.35,45.05 69.975,45.05 v1(70.1,45.175) ; v1@70.156,45.231 L302.2@70.156,45.956 ; R319.1@73.7,41.9 v1@73.7,43.05
  other v1: 73.7,43.1
VDDCR: C307.1 C308.1 C309.1 C310.2 L301.1 TP300.1 U333.6 U333.22 U333.32 | length 20.7
  Top Layer w0.203: v1(60.5,51) 60.541,50.959 61.691,50.959 U333.32@61.7,50.95 ; v1(65.3,54) 65.312,53.988 65.312,53.688 65.45,53.55 U333.22@65.45,53.2
  Top Layer w0.254: U333.6@69.7,48.45 70.35,48.45 70.6,48.2 v1(71.1,48.2)
  Top Layer w0.508: v1(71.1,48.2) 71.2,48.1 C307.1@72.1,48.1
  Inner-1 w0.508: v1(60.5,51) 61.8,51 63.475,52.675 65.275,52.675 65.3,52.7 v1(65.3,54) ; 69.6,48.2 v1(71.1,48.2)
  Inner-1 w0.635: v1(61.4,44.1) 61.9,44.6 61.9,45.6
  Bottom Layer w0.203: C309.1@65.45,53.35 C309.1@65.5,53.3 ; v1@71.1,48.4 71.3,48.2 71.7,48.2 72,47.9 TP300.1@72.6,47.9
  Bottom Layer w0.508: v1(60.5,51) 61.1,50.4 C310.2@61.6,50.4 ; v1(65.3,54) 65.3,53.9 65.45,53.75 C309.1@65.45,53.35 ; C308.1@69.9,48.2 v1(71.1,48.2)
  Bottom Layer w0.635: v1(61.4,44.1) L301.1@62.4,44.1
VPOE+: C329.1 C401.1 C404.1 C409.1 C413.1 C414.1 C415.1 D401.C D402.C D403.C L400.1 L401.2 R401.1 R402.2 R412.2 T301.18 T301.21 TP400.1 U400.1 U404.1 U406.17 | length 149.6
  Top Layer w0.254: U406.17@42.7,33.35 v1(43.65,33.35)
  Top Layer w0.305: v1(16.9,27.9) 17.1,27.7 R412.2@17.7,27.7 ; v1(18.2,21.4) R402.2@18.2,23.6 ; v1(23.8,29.5) U404.1@24.5,29.5 ; U400.1@24.5,23.45 24.5,23 25.2,22.3 R401.1@26,22.3
  Top Layer w0.508: v1(26,21.4) R401.1@26,22.3 ; T301.18@73.815,22.96 73.815,24.415 74.4,25 77.6,25 ; v1(77.6,26.7) 77.6,25 ; T301.21@77.625,22.96 77.6,22.985 77.6,25
  Top Layer w0.635: v1(15.7,26) 15.7,24.948 C401.1@16.048,24.6 ; C401.1@16.048,24.308 16.317,24.038 16.317,21.883 L400.1@16.4,21.8 ; L400.1@16.5,21.4 v1(18.2,21.4) ; v1(26,21.4) 26.8,21.4 27.1,21.7 D402.C@28.5,21.7 ; D403.C@37.9,22 v1(39.1,22) ; v1@43.7,33.3 45.1,31.9 v1(45.1,24.8)
  Inner-1 w0.508: v1(23.8,29.5) 25.2,30.9 29,30.9 29.5,31.4 32.7,31.4 33.4,30.7 33.4,22
  Inner-1 w0.635: v1(26,21.4) 31.3,21.4 31.9,22 33.4,22 v1(39.1,22) ; v1(45.1,24.8) 45.8,25.5 45.8,26.928 46.572,27.7 v1(51.5,27.7) v1(52.7,27.7) 57.4,27.7 57.6,27.9 60.6,27.9 61.3,27.2 75.5,27.2 76,26.7 v1(77.6,26.7)
  Bottom Layer w0.203: TP400.1@46.2,22.3 46.2,22.6 47.5,23.9 D401.C@47.5,24.1
  Bottom Layer w0.305: v1(15.7,26) 16.9,27.2 v1(16.9,27.9)
  Bottom Layer w0.508: v1(23.8,29.5) 25.189,28.111 26.011,28.111 26.5,28.6 C409.1@26.5,29.75 ; L401.2@56.05,27.25 L401.2@56.1,27.3
  Bottom Layer w0.635: v1(18.2,21.4) v1(26,21.4) 29.85,21.4 C414.1@30,21.55 ; C415.1@37.6,21.65 38.75,21.65 v1(39.1,22) 39.1,23.6 40.3,24.8 v1(45.1,24.8) 47.325,24.8 D401.C@47.5,24.975 ; C413.1@42.5,33.35 v1(43.65,33.35) ; D401.C@47.4,24.4 47.8,24.8 48.6,24.8 v1(51.5,27.7) v1(52.7,27.7) 53.2,27.7 53.65,27.25 C404.1@54,27.25 L401.2@56.05,27.25
  Bottom Layer w0.762: C329.1@77.6,25.7 v1(77.6,26.7)
VPOE-: C404.2 D401.A L402.2 R403.1 R405.1 R406.1 R407.1 R408.2 R409.2 TP405.1 U400.4 U400.5 U400.21 | length 41.6
  Top Layer w0.305: v1(19.7,27.1) R407.1@19.7,28 ; U400.5@24.5,26 25.5,26 R405.1@26,26.5
  Bottom Layer w0.203: D401.A@48.2,29.1 TP405.1@48.2,30.4
  Bottom Layer w0.508: R403.1@25.9,24.4 R408.2@25.9,25.3 R406.1@25.9,26.4
  Bottom Layer w0.635: v1(19.7,27.1) 20.5,26.3 R409.2@20.6,26.3 21.418,26.3 21.418,25.817 v3(21.3,25.7)
  Bottom Layer w1: R406.1@26,26.5 29.9,30.4 46,30.4 47.6,28.8 47.6,29.1 48.2,29.1 L402.2@56.1,29.1 ; D401.A@47.6,28.3 D401.A@47.6,28.6
  other v1: 26.848,27.357 27.448,27.957 29.948,30.357 32.348,30.357
  other v3: 21.3,23.8 23.1,23.8 22.2,24.3 21.3,24.7 23.1,24.7 22.5,25.5
  other v4: 23.5,25.5 23,26
pads on no net: D400.37 FI1.1 FI2.1 FI3.1 FI11.1 FI12.1 FI13.1 T300.7 T300.8 T300.9 T300.10 T300.11 T300.12 T301.7 T301.8 T301.9 T301.10 T301.11 T301.12 U1.A7 U1.A10 U1.A11 U1.A12 U1.A14 U1.B1 U1.B7 U1.B8 U1.B10 U1.B14 U1.C6 U1.D2 U1.D4 U1.D11 U1.D14 U1.E1 U1.E2 U1.E4 U1.E10 U1.E11 U1.F2 U1.F5 U1.G2 U1.G4 U1.G11 U1.H2 U1.H3 U1.H12 U1.J1 U1.J3 U1.J4 U1.J11 U1.J12 U1.K10 U1.K12 U1.L3 U1.L7 U1.L9 U1.L11 U1.L12 U1.M2 U1.M7 U1.M8 U1.M9 U1.M10 U1.M12 U1.N3 U1.N12 U1.N13 U1.P2 U1.P9 U1.P10 U1.P12 U1.P13 U1.P14 U3.1 U3.2 U3.3 U3.7 U3.9 U201.E2 U333.2 U333.3 U333.27 U400.14 U400.15 U400.20 U401.3 U401.5 U401.8 U404.5 U406.8 U406.14 U406.15 U406.16 U406.18 U406.19 U406.20 U406.22 U406.23 U406.24 U406.25 U406.26 U406.27 U406.28 U406.29 U406.35 U406.36 U406.42 U406.47 U406.52 U406.56 U408.6 U408.11 U409.1 U700.12 U700.17 U700.19 X2.7 X3.91 X3.92 X300.MH1 X300.MH2 X301.MH1 X301.MH2 X500.91 X500.92 X500.93 X500.94 X700.98 X700.99
copper on no net: | length 56
  Top Layer w0.127: 81,53.9 81,55.1 ; 82,53.9 82,55.1 ; 83,53.9 83,55.1 ; 80,53.9 84,53.9 84,55.1 80,55.1 80,53.9
  Inner-1 w0.152: 81,53.9 81,55.1 ; 82,53.9 82,55.1 ; 83,53.9 83,55.1 ; 80,53.9 80,55.1 84,55.1 84,53.9 80,53.9
  Inner_GND w0.152: 81,53.9 81,55.1 ; 82,53.9 82,55.1 ; 83,53.9 83,55.1 ; 80,53.9 80,55.1 84,55.1 84,53.9 80,53.9
  Bottom Layer w0.127: 81,53.9 81,55.1 ; 82,53.9 82,55.1 ; 83,53.9 83,55.1 ; 80,53.9 84,53.9 84,55.1 80,55.1 80,53.9

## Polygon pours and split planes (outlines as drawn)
GND on Inner_GND "L3_GND" (solid, remove dead copper, pour order 82): 85,39.6 45.954,39.6 45.954,41.722 42.954,44.722 33.254,44.722 30.654,42.122 29.154,40.622 22.546,40.622 14.224,32.3 6,32.3 3.1,29.4 3.1,20.7 4.7,19.1 5.2,19.1 5.2,10 0,10 0,56.7 22.5,56.7 22.5,81 62.5,81 62.5,57 85,57.051
AGND on Inner_GND "L3-AGND" (solid, remove dead copper, pour order 96): 6.172,10 26.886,10 26.886,17.486 25.7,18.672 11.572,18.672 6.172,18.672
EARTH on Inner_GND "L3_EARTH" (solid, remove dead copper, pour order 94): 29,16.9 29,7.7 0,7.7 0,0 85,0 85.104,24.2 49.7,24.2 42.4,16.9
RTN on Inner_GND "L3_RTN" (solid, remove dead copper, pour order 88): 45.8,23.3 45.8,34.4 43.6,36.6 43.6,40.9 41.9,42.6 34.1,42.6 30,38.5 25.34,38.5 14.94,28.1 10.5,28.1 8.7,26.3 5.1,26.3 5.1,21.6 5.4,21.3 26.3,21.3 28.4,19.2 41.7,19.2
VPOE- on Inner_GND "L3_VPOE-" (solid, remove dead copper, pour order 84): 22.7,31.5 19.2,28 19.2,21.3 33,21.3 33,31.5
GND on Bottom Layer "L4_GND" (solid, remove dead copper, pour order 100): 85,39.6 66.5,39.6 45.8,39.6 45.8,41.7 42.8,44.7 32.2,44.7 28.1,40.6 22.6,40.6 14.3,32.3 6,32.3 3.1,29.4 3.1,20.7 4.7,19.1 5.2,19.1 5.2,10 0,10 0,56.9 22.5,56.9 22.5,81 62.5,81 62.5,57 85,57
AGND on Bottom Layer "L4-AGND" (solid, remove dead copper, pour order 110): 6.2,10 26.9,10 26.9,17.5 25.7,18.7 6.2,18.7
EARTH on Bottom Layer "L4_EARTH" (solid, remove dead copper, pour order 106): 28.9,16.9 28.9,7.7 0,7.7 0,0 85,0 85.104,24.2 47.2,24.2 47.2,16.9
3V3 on Bottom Layer "L4_3V3MCU" (solid, remove dead copper, pour order 98): 24.1,57 59.8,57 59.8,79.3 24.1,79.3
RTN on Bottom Layer "L4_RTN" (solid, remove dead copper, pour order 104): 45.8,22.9 45.8,34.4 43.6,36.6 43.6,40.9 41.9,42.6 34.1,42.6 30,38.5 25.327,38.5 14.927,28.1 10.5,28.1 8.7,26.3 5.1,26.3 5.1,21.6 5.4,21.3 26.3,21.3 28.4,19.2 42.1,19.2
VPOE- on Bottom Layer "L4_VPOE-" (solid, remove dead copper, pour order 102): 22.1,31.5 19.2,28.6 19.2,21.2 33,21.2 33,31.5
RTN on Inner-1 "L3_RTN" (solid, remove dead copper, pour order 74): 45.4,23 45.4,34.8 43.6,36.6 43.6,40.9 41.9,42.6 34.1,42.6 30,38.5 25.3,38.5 14.9,28.1 10.5,28.1 8.7,26.3 5.1,26.3 5.1,21.6 5.4,21.3 26.3,21.3 28.4,19.2 41.6,19.2
EARTH on Inner-1 "L2_EARTH" (solid, remove dead copper, pour order 77): 29,16.9 29,7.7 0,7.7 0,0 85,0 85.104,24.203 48.495,23.995 41.4,16.9
GND on Inner-1 "L2_GND" (solid, remove dead copper, pour order 68): 85,39.6 45.8,39.6 45.8,41.7 42.8,44.7 33.1,44.7 29,40.6 20.724,40.6 12.424,32.3 6,32.3 3.1,29.4 3.1,20.7 4.7,19.1 5.2,19.1 5.2,10 0,10 0,56.8 22.5,56.8 22.5,81 62.5,81 62.5,56.9 85,56.9
3V3 on Inner-1 "L2_3V3" (solid, remove dead copper, pour order 67): 73,45.5 56,45.5 55.7,45.8 22.2,45.8 22.2,50.9 24.1,50.9 24.1,79.4 59.8,79.4 59.8,54.4 73,54.4
VDDCR on Inner-1 "L2_VDDCR" (solid, remove dead copper, pour order 66): 61.3,45.1 61.3,51.8 62.4,52.9 69.475,52.9 70,52.375 70,45.907 69.207,45.1
AGND on Inner-1 "L2-AGND" (solid, remove dead copper, pour order 79): 6.172,10 26.772,10 26.772,17.472 25.872,18.372 11.872,18.372 11.572,18.672 6.172,18.672
VPOE+ on Inner-1 "L2_VPOE+" (solid, remove dead copper, pour order 73): 37.5,29.4 46.8,29.4 46.8,26 42.3,21.5 37.5,21.5
VPOE- on Inner-1 "L2_VPOE-" (solid, remove dead copper, pour order 72): 22.7,31.5 19.2,28 19.2,21.3 33,21.3 33,31.5
GND on Inner-1 "L2_BRIDGEGND" (solid, remove dead copper, pour order 64): 63,52 63,46.4 68.75,46.4 68.75,52
GND on Top Layer "L1_GND" (solid, remove dead copper, pour order 55): 85,39.6 45.8,39.6 45.8,41.7 42.8,44.7 33.1,44.7 30.5,42.1 29,40.6 22.5,40.6 14.2,32.3 6,32.3 3.1,29.4 3.1,20.7 4.7,19.1 5.2,19.096 5.2,10 0,10 0,56.8 22.5,56.8 22.5,81 62.5,81 62.5,56.8 85,56.8
RTN on Top Layer "L1_RTN" (solid, remove dead copper, pour order 59): 45.6,23.2 45.6,34.6 43.6,36.6 43.6,40.9 41.9,42.6 34.1,42.6 32.7,41.2 30,38.5 29.38,38.5 25.416,38.5 15.556,28.64 11.04,28.64 8.7,26.3 5.1,26.3 5.1,21.6 5.4,21.3 26.3,21.3 28.4,19.2 41.6,19.2
EARTH on Top Layer "L1_EARTH" (solid, remove dead copper, pour order 61): 29,16.9 29,7.7 0,7.7 0,0 85,0 85.104,24.2 47.2,24.2 47.2,16.9
AGND on Top Layer "L1-AGND" (solid, remove dead copper, pour order 62): 6.172,10 26.772,10 26.772,17.472 25.872,18.372 11.872,18.372 11.572,18.672 6.172,18.672
VPOE- on Top Layer "L1_VPOE-" (solid, remove dead copper, pour order 57): 19.2,31.5 19.2,21.5 25,21.5 33,21.5 33,31.5

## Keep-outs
Keep-Out Layer:
  the board outline again, w0.2

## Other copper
Top Layer:
  rectangle net +12V: 45.8,42.1 46.7,45.1
  region net GND: 69.075,52.525 62.25,52.525 62.25,45.775 69.075,45.775
  region net RTN: 41.825,38.85 35.5,38.85 35.5,32.4 41.825,32.4
  region net VPOE-: 25.2,26.3 23.6,26.3 23.6,25.15 25.2,25.15
  region net VPOE-: 23.75,26.3 20.8,26.3 20.8,23.35 23.75,23.35
  region net RTN: 20.5,26.4 19,26.4 19,25.2 20.5,25.2
  region net NetL403_1: 24.2,30.9 24.2,31.8 20.4,31.8 20.4,30.9
  rectangle net RTN: 41.3,34.7 42.1,36.8
  pour cut-out: 66.5,43.8 67.6,43.8 68.4,44.6 69.2,44.6 69.8,44 69.8,42.7 68.4,41.3 67.2,41.3 66.5,42
  pour cut-out: 81.3,39.3 81.3,40.5 79.3,40.5 79.3,39.3
  pour cut-out: 74,39.4 75.2,40.6 76.3,40.6 76.3,39.4
  pour cut-out: 54.6,40.8 54.6,38.1 57,38.1 57,40.8
  pour cut-out: 60.4,44 58.411,42.2 58.411,36.2 60.8,36.2 60.8,42 64.8,42 64.8,44
  text "Layer 1 (top)" at 37.2,83 h2
  text "1" at 80.3,54.1 h1.3
Inner-1:
  pour cut-out: 68.2,43.9 66.8,42.5 66.8,41.8 67.7,40.9 70.2,40.9 72,39.1 81.3,39.1 81.3,40.7 80.8,41.2 79.6,41.2 77.9,42.9 74,42.9 73,43.9
  pour cut-out: 68.9,44.1
  text "Layer 2" at 37.2,83 h2
  text "2" at 81.2,54.1 h1.3
Inner_GND:
  text "Layer 3" at 37.2,83 h2
  text "3" at 82.2,54.1 h1.3
Bottom Layer:
  region net PW36: 63.5,28.5 62.1,28.5 62.1,27.7 63.5,27.7
  region net NetC403_1: 60.3,22.8 60.3,21.1 62.8,21.1 62.8,22.8
  region net NetC403_2: 61.2,27.5 61.2,25.8 62.755,25.8 62.755,27.5
  region net PW78: 61.2,25.6 61.2,23 62.8,23 62.8,25.6
  region net PW45: 69,25.6 69,23 70.6,23 70.6,25.6
  region net NetC403_1: 68.945,22.8 68.945,21.2 70.1,21.2 70.1,22.8
  region net NetC403_2: 68.945,27.3 68.945,25.8 70.2,25.8 70.2,27.3
  rectangle net PW12: 66.7,19.2 70,20.3
  region net PW36: 65.1,20.3 59.3,20.3 59.3,18.9 65.1,18.9
  region net PW36: 65.1,29.1 62.1,29.1 62.1,28.1 65.1,28.1
  rectangle net PW12: 66.7,28.1 70.4,29.1
  rectangle net NetC403_1: 63.1,21.1 68.6,22.8
  rectangle net NetC403_2: 63.1,25.6 68.6,27.3
  pour cut-out: 57.4,37 60.5,37 60.5,39.8 57.4,39.8
  pour cut-out: 56.5,43.9 54,41.4 54,37 56.9,37 56.9,41.4 57.6,42.1 64.6,42.1 64.6,43.9
  pour cut-out: 46.4,12.6 42.3,12.6 42.3,18.5 42.9,19.1 45.1,19.1 48,22 49,22 49.5,21.5 49.5,15.7
  pour cut-out: 60.5,17 62.5,19 74.5,19 76,20.5 78,20.5 79,19.5 79,14.5 60.5,14.5
  text "Layer 4 (bottom)" at 37.3,83 h2
  text "4" at 83.8,54.1 h1.3
  text ".PRJ_Title" at 84.3,2.7 h2
  text ".PRJ_Revision" at 78.4,0.8 h2
  text "Rev." at 82.5,0.799 h2

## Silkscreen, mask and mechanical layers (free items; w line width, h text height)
Top Overlay:
  circle w0.254: c23.8,77.6 r0.283
  lines w0.2: 76.5,3.8 83.2,3.8 83.2,16.4 76.5,16.4 76.5,3.8
  text "Silkscreen (top)" at 37.2,83 h2
  text ".PRJ_Revision" at 82.7,14 h2 r90
  text "Rev." at 82.7,9.9 h2 r90
  text "Headset" at 16.1,7.7 h1.52
  text "PD" at 43.2,7.5 h1.52
  text "PSE" at 66.2,7.5 h1.52
  text ".PRJ_Title" at 81,4.3 h1.7 r90
  text "PUNQTUM" at 79.015,3.8 h2.5 r90
Bottom Overlay:
  text "Silkscreen (bottom)" at 50.5,83 h2
Outline:
  lines w0.051: 172.2,9 172.2,9
  lines w0.2: 0,0 0,56 21.5,56 ccw(c21.5,57) 22.5,57 22.5,81 62.5,81 62.5,57 ccw(c63.5,57) 63.5,56 85,56 85,0 0,0
Top Assembly:
  circle w0.1: c33.4,51.8 r0.316
  circle w0.1: c24.1,79.4 r0.316
  circle w0.1: c69.1,43.9 r0.316
  circle w0.1: c43.9,51.5 r0.316
  lines w0.1: 72,52.1 72.9,52.1 73.5,52.7 77.2,52.7
  lines w0.254: 2.4,89.6 44.4,89.6
  text "(TOP VIEW)" at 34.8,90.6 h2
  text ".PRJ_Title" at 2.55,90.4 h3
  text "Rev." at 24.5,90.282 h3
  text ".PRJ_Revision" at 30.3,90.284 h3
  text "Assembly (top)" at 37.2,83 h2
Bottom Assembly:
  circle w0.051: c37.8,51.8 r0.283
  lines w0.254: 35.6,89.3 82.2,89.3
  text "(BOTTOM VIEW)" at 49.3,90.728 h2
  text ".PRJ_Title" at 82.05,90.5 h3
  text ".PRJ_Revision" at 54,90.384 h3
  text "Rev." at 60.1,90.382 h3
  text "Assembly (bottom)" at 50.1,83 h2
Dimensions:
  lines w0.1: 21,40.5 23,42.5 32,42.5 ; 66.1,51.3 75.1,51.3 77.1,49.3
  lines w0.254: 2.8,101.8 53,101.8
  text "(TOP VIEW)" at 43.3,102.9 h2
  text ".PRJ_Title" at 2.75,102.722 h4
  text "Rev." at 30.4,102.564 h4
  text ".PRJ_Revision" at 38.4,102.566 h4
  text "(all dimensions in mm)" at 2.75,98.6 h2
  text "D=6.8mm" at 66.6,51.6 h2
  text "D=6.8mm" at 23.7,42.8 h2
Drill Drawing:
  drawing of 281 lines, arcs and shapes, not listed
  text "Layer" at 112.539,97.943 h1.75
  text "Name" at 119.851,97.943 h1.75
  text "Material" at 133.981,97.943 h1.75
  text "Thickness" at 146.684,97.943 h1.75
  text "Constant" at 157.117,97.943 h1.75
  text "Board Layer Stack" at 166.778,97.943 h1.75
  text "Top Overlay" at 119.851,94.443 h1.75
  text "Top Solder" at 119.851,90.943 h1.75
  text "Solder Resist" at 133.981,90.943 h1.75
  text "0.017mm" at 146.684,90.943 h1.75
  text "3.3" at 157.117,90.943 h1.75
  text "1" at 112.539,87.443 h1.75
  text "Top Layer" at 119.851,87.443 h1.75
  text "Copper" at 133.981,87.443 h1.75
  text "0.035mm" at 146.684,87.443 h1.75
  text "Dielectric1" at 119.851,83.943 h1.75
  text "0.108mm" at 146.684,83.943 h1.75
  text "3.6" at 157.117,83.943 h1.75
  text "2" at 112.537,80.443 h1.75
  text "Inner-1" at 119.851,80.443 h1.75
  text "Copper" at 133.981,80.443 h1.75
  text "0.035mm" at 146.684,80.443 h1.75
  text "Dielectric2" at 119.851,76.943 h1.75
  text "FR-4" at 133.981,76.943 h1.75
  text "1.200mm" at 146.684,76.943 h1.75
  text "4.2" at 157.117,76.943 h1.75
  text "3" at 112.539,73.443 h1.75
  text "Inner_GND" at 119.851,73.443 h1.75
  text "Copper" at 133.981,73.443 h1.75
  text "0.035mm" at 146.684,73.443 h1.75
  text "Dielectric 3" at 119.851,69.943 h1.75
  text "0.108mm" at 146.684,69.943 h1.75
  text "3.6" at 157.117,69.943 h1.75
  text "4" at 112.539,66.443 h1.75
  text "Bottom Layer" at 119.851,66.443 h1.75
  text "Copper" at 133.981,66.443 h1.75
  text "0.035mm" at 146.684,66.443 h1.75
  text "Bottom Solder" at 119.851,62.943 h1.75
  text "Solder Resist" at 133.981,62.943 h1.75
  text "0.017mm" at 146.684,62.943 h1.75
  text "3.3" at 157.117,62.943 h1.75
  text "Bottom Overlay" at 119.851,59.443 h1.75
  text "Symbol" at 112.749,37.417 h2.1
  text "Count" at 120.955,37.417 h2.1
  text "Hole Size" at 129.451,37.417 h2.1
  text "Plated" at 146.255,37.417 h2.1
  text "Hole Type" at 153.459,37.417 h2.1
  text "Drill Layer Pair" at 163.947,37.417 h2.1
  text "Via/Pad" at 183.804,37.417 h2.1
  text "Pad Shape" at 192.397,37.417 h2.1
  text "153" at 120.955,33.802 h1.75
  text "0.150mm (5.91mil)" at 129.451,33.802 h1.75
  text "PTH" at 146.255,33.802 h1.75
  text "Round" at 153.459,33.802 h1.75
  text "Top Layer - Inner-1" at 163.947,33.802 h1.75
  text "Via" at 183.804,33.802 h1.75
  text "Rounded" at 192.397,33.802 h1.75
  text "41" at 120.955,30.188 h1.75
  text "0.200mm (7.87mil)" at 129.451,30.188 h1.75
  text "PTH" at 146.255,30.188 h1.75
  text "Round" at 153.459,30.188 h1.75
  text "Top Layer - Bottom Layer" at 163.947,30.188 h1.75
  text "Via" at 183.804,30.188 h1.75
  text "Rounded" at 192.397,30.188 h1.75
  text "461" at 120.955,26.573 h1.75
  text "0.250mm (9.84mil)" at 129.451,26.573 h1.75
  text "PTH" at 146.255,26.573 h1.75
  text "Round" at 153.459,26.573 h1.75
  text "Top Layer - Bottom Layer" at 163.947,26.573 h1.75
  text "Via" at 183.804,26.573 h1.75
  text "Rounded" at 192.397,26.573 h1.75
  text "7" at 120.955,22.959 h1.75
  text "0.800mm (31.50mil)" at 129.451,22.959 h1.75
  text "PTH" at 146.255,22.959 h1.75
  text "Round" at 153.459,22.959 h1.75
  text "Top Layer - Bottom Layer" at 163.947,22.959 h1.75
  text "Pad" at 183.804,22.959 h1.75
  text "(Mixed)" at 192.397,22.959 h1.75
  text "18" at 120.955,19.344 h1.75
  text "0.900mm (35.43mil)" at 129.451,19.344 h1.75
  text "PTH" at 146.255,19.344 h1.75
  text "Round" at 153.459,19.344 h1.75
  text "Top Layer - Bottom Layer" at 163.947,19.344 h1.75
  text "Pad" at 183.804,19.344 h1.75
  text "(Mixed)" at 192.397,19.344 h1.75
  text "9" at 120.955,15.729 h1.75
  text "1.016mm (40.00mil)" at 129.451,15.729 h1.75
  text "PTH" at 146.255,15.729 h1.75
  text "Round" at 153.459,15.729 h1.75
  text "Top Layer - Bottom Layer" at 163.947,15.729 h1.75
  text "(Mixed)" at 183.804,15.729 h1.75
  text "(Mixed)" at 192.397,15.729 h1.75
  text "3" at 120.955,12.115 h1.75
  text "1.200mm (47.24mil)" at 129.451,12.115 h1.75
  text "PTH" at 146.255,12.115 h1.75
  text "Round" at 153.459,12.115 h1.75
  text "Top Layer - Bottom Layer" at 163.947,12.115 h1.75
  text "Pad" at 183.804,12.115 h1.75
  text "Rounded" at 192.397,12.115 h1.75
  text "4" at 120.955,8.5 h1.75
  text "1.600mm (62.99mil)" at 129.451,8.5 h1.75
  text "NPTH" at 146.255,8.5 h1.75
  text "Round" at 153.459,8.5 h1.75
  text "Top Layer - Bottom Layer" at 163.947,8.5 h1.75
  text "Pad" at 183.804,8.5 h1.75
  text "Rounded" at 192.397,8.5 h1.75
  text "4" at 120.955,4.886 h1.75
  text "1.600mm (62.99mil)" at 129.451,4.886 h1.75
  text "PTH" at 146.255,4.886 h1.75
  text "Round" at 153.459,4.886 h1.75
  text "Top Layer - Bottom Layer" at 163.947,4.886 h1.75
  text "Pad" at 183.804,4.886 h1.75
  text "Rounded" at 192.397,4.886 h1.75
  text "2" at 120.955,1.271 h1.75
  text "6.800mm (267.72mil)" at 129.451,1.271 h1.75
  text "NPTH" at 146.255,1.271 h1.75
  text "Round" at 153.459,1.271 h1.75
  text "Top Layer - Bottom Layer" at 163.947,1.271 h1.75
  text "Pad" at 183.804,1.271 h1.75
  text "Rounded" at 192.397,1.271 h1.75
  text "702 Total" at 120.955,-2.343 h1.75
